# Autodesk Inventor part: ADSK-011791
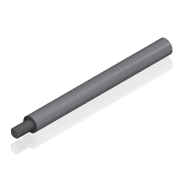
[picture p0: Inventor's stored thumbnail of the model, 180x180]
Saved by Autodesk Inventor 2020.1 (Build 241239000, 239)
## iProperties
Created: 1999-11
Part Number: ADSK-011791
Material: Acier doux
Document SubType Name: Modeling
Designer: kcovelli
Density: 7.86 g/cm^3
Appearance: Metal-Steel(Polish)
Mass: 267.63 g
Surface Area: 91.2233 cm^2
Volume: 34.0496 cm^3
Control State: 0
Master: False
Checked Out: False
Shininess: 0.0
Length Units: 11269
Angle Units: 11279
Time Units: 11290
Mass Units: 11283
Length Display Precision: 3
Angle Display Precision: 2
Compacted: True
Dimensions: 16x181x16 mm
Mass: 0,268 kg
VLT_Material: Acier doux
Density: 0.0
Volumn: 0.0
Area: 0.0
PropertySet Name: Model Information
Author: kcovelli
Revision Number: -
Title: ADSK-011791
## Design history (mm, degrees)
feature "Gewinde1" dims "d11" = 18, "d12" = 0
chamfer "Fase1" distance "d8" = 1; stored, may be unused: second distance "d9" = 2, angle "d10" = 45 deg
node "Solide1"
  node "Extrusion1" dims "d0" = 152, "d1" = 0
  node "Extrusion2" dims "d2" = 10, "d3" = 0
  node "Extrusion3" dims "d5" = 19, "d6" = 0
sketch "Sketch1"
  geometry: C1 r 8 at (-1.105, 0)
  constraints: 1 centre point
  dimensions: "d7" = 16 diameter of C1
sketch "Sketch2"
  geometry: C1 r 8 at (0, 0) reference
sketch "Sketch3"
  geometry: C1 r 8 at (0, 0) reference; C2 r 5 at (0, 0)
  constraints: 1 centre point, 1 coincident
  dimensions: "d4" = 10 diameter of C2
node "Corps solides"
node "Corps surfaciques"
